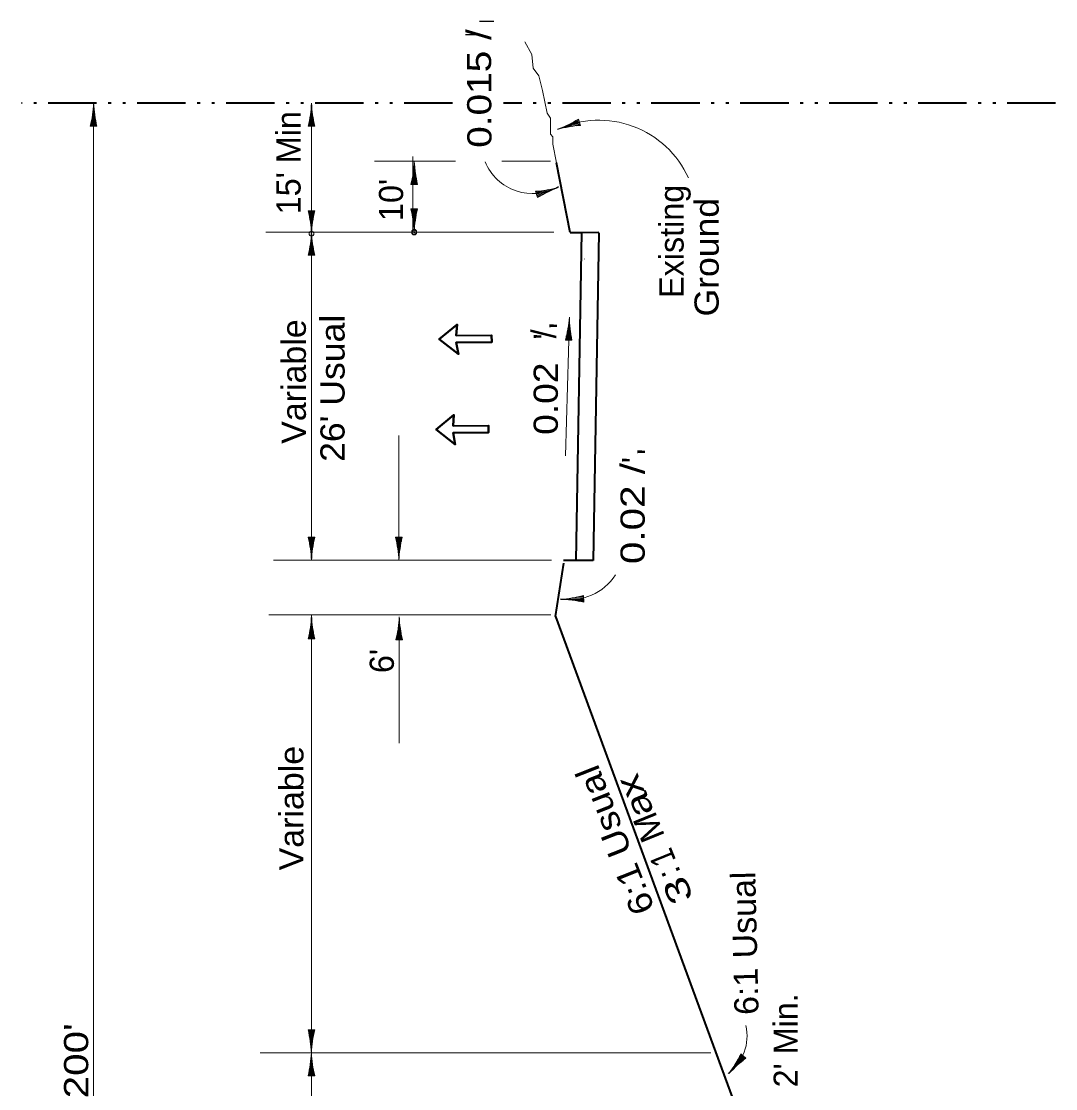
# Model space of a CAD drawing. Extents: x 2363427 to 2368559, y 6957299 to 6980140.
# Drawn here: x 2364654 to 2365253, y 6959501 to 6960119 of the extents above; entities that cross this region are included whole.
import ezdxf
from ezdxf.enums import TextEntityAlignment as Align

# ---------------------------------------------------------------- set-up
doc = ezdxf.new("R2010")
doc.units = 0
doc.header["$LTSCALE"] = 5.6
doc.header["$PDMODE"] = 32
doc.header["$PDSIZE"] = 2.8
doc.linetypes.add('DASH_DOUBLE_DOT', pattern=[9.2, 5, -1.2, 0.3, -1.2, 0.3, -1.2])
doc.linetypes.add('MEDIUM_DASHED', pattern=[4.5, 3, -1.5])
for name, color, linetype, lineweight in [('1', 7, 'Continuous', 13), ('3', 7, 'Continuous', 35), ('4', 7, 'Continuous', 13), ('40', 7, 'Continuous', 35), ('48', 7, 'Continuous', 25), ('6', 7, 'Continuous', 13), ('8', 7, 'Continuous', 13)]:
    doc.layers.add(name, color=color, linetype=linetype, lineweight=lineweight)

msp = doc.modelspace()

# ---------------------------------------------------------------- linework, layer by layer
at = {"layer": '1'}
for p, q in [((2364977.084, 6960060.54), (2364965.138, 6960056.646)), ((2364977.239, 6960060.065), (2364969.053, 6960057.397)), ((2364976.929, 6960061.015), (2364969.941, 6960058.737)), ((2364976.774, 6960061.491), (2364972.708, 6960060.165)), ((2364976.619, 6960061.967), (2364975.112, 6960061.475)), ((2364976.51, 6960062.299), (2364977.698, 6960058.657)), ((2364977.394, 6960059.589), (2364972.772, 6960058.083)), ((2364977.549, 6960059.114), (2364975.284, 6960058.376)), ((2365071.926, 6959519.653), (2365063.908, 6959509.979)), ((2365072.31, 6959519.333), (2365066.816, 6959512.705)), ((2365071.54, 6959519.971), (2365066.85, 6959514.313)), ((2365071.156, 6959520.291), (2365068.426, 6959516.998)), ((2365072.696, 6959519.015), (2365069.592, 6959515.271)), ((2365070.77, 6959520.609), (2365069.759, 6959519.389)), ((2365070.501, 6959520.833), (2365073.45, 6959518.389)), ((2365073.08, 6959518.695), (2365071.56, 6959516.861))]:
    msp.add_line(p, q, dxfattribs=at)
at = {"layer": '1', "linetype": 'MEDIUM_DASHED'}
msp.add_lwpolyline([(2364963.772, 6960036.875), (2364961.718, 6960047.707), (2364961.718, 6960052.041), (2364960.366, 6960053.487), (2364960.366, 6960059.267), (2364960.366, 6960062.879), (2364958.338, 6960065.769), (2364956.986, 6960072.271), (2364955.634, 6960078.773), (2364953.605, 6960087.443), (2364950.225, 6960091.777), (2364949.549, 6960099.725), (2364945.492, 6960106.949)], dxfattribs=at)
at = {"layer": '1'}
for centre, radius, start, end in [((2364988.349, 6960004.852), 56.809, 24.26661, 114.90949), ((2364938.688, 6960123.814), 72.212, 290.89929, 301.58534), ((2364983.396, 6959986.67), 72.212, 94.52612, 105.21217), ((2365047.078, 6959531.078), 27.012, 306.76831, 13.14994), ((2365005.667, 6959552.632), 72.212, 323.18777, 333.87382), ((2365116.722, 6959460.577), 72.212, 126.81461, 137.50066)]:
    msp.add_arc(centre, radius, start, end, dxfattribs=at)
at = {"layer": '3', "linetype": 'DASH_DOUBLE_DOT'}
for p, q in [((2364903.617, 6960071.447), (2364653.955, 6960071.447)), ((2365252.758, 6960071.447), (2364933.046, 6960071.447))]:
    msp.add_line(p, q, dxfattribs=at)
at = {"layer": '3'}
for p, q in [((2364971.652, 6959996.693), (2364963.772, 6960036.875)), ((2364971.652, 6959996.693), (2364978.244, 6959996.665)), ((2364978.244, 6959996.665), (2364974.924, 6959806.63)), ((2364978.244, 6959996.665), (2364988.247, 6959996.757)), ((2364988.242, 6959996.49), (2364984.924, 6959806.542)), ((2364984.925, 6959806.629), (2364967.902, 6959806.631)), ((2364963.114, 6959774.14), (2364968.1, 6959804.984)), ((2364963.114, 6959774.14), (2365067.63, 6959490.027))]:
    msp.add_line(p, q, dxfattribs=at)
at = {"layer": '3', "lineweight": 13}
for p, q in [((2364962.238, 6959996.759), (2364795.534, 6959996.759)), ((2364978.248, 6959996.709), (2364978.244, 6959996.665)), ((2364980.071, 6959981.22), (2364979.949, 6959981.334)), ((2364968.937, 6959867.329), (2364971.212, 6959947.583)), ((2364970.4, 6959934.289), (2364970.644, 6959942.895)), ((2364970.9, 6959934.275), (2364971.256, 6959946.833)), ((2364969.401, 6959934.317), (2364969.468, 6959936.697)), ((2364969.9, 6959934.303), (2364970.038, 6959939.163)), ((2364971.4, 6959934.261), (2364971.608, 6959941.607)), ((2364971.9, 6959934.247), (2364972.021, 6959938.521)), ((2364972.75, 6959934.223), (2364968.921, 6959934.331)), ((2364972.4, 6959934.233), (2364972.444, 6959935.817)), ((2364960.92, 6959806.759), (2364799.934, 6959806.759)), ((2364969.506, 6959806.533), (2364969.506, 6959806.631)), ((2365053.112, 6959521.447), (2364792.272, 6959521.447))]:
    msp.add_line(p, q, dxfattribs=at)
for centre, start, end in [((2364899.219, 6959953.208), 344.84626, 355.53231), ((2365043.409, 6959949.119), 181.21943, 191.90548)]:
    msp.add_arc(centre, 72.212, start, end, dxfattribs=at)
at = {"layer": '4', "lineweight": 25}
for p, q in [((2364927.449, 6960118.911), (2364919.288, 6960118.911)), ((2364919.32, 6960111.075), (2364911.159, 6960111.075))]:
    msp.add_line(p, q, dxfattribs=at)
at = {"layer": '4'}
for p, q in [((2364905.299, 6960037.877), (2364858.467, 6960037.877)), ((2364881.36, 6960024.479), (2364881.36, 6960037.043)), ((2364881.36, 6960024.479), (2364881.36, 6960037.043)), ((2364960.343, 6960037.877), (2364932.205, 6960037.877)), ((2364880.86, 6960024.479), (2364880.86, 6960031.829)), ((2364880.86, 6960024.479), (2364880.86, 6960031.829)), ((2364881.86, 6960024.479), (2364881.86, 6960033.088)), ((2364881.86, 6960024.479), (2364881.86, 6960033.088)), ((2364882.36, 6960024.479), (2364882.36, 6960029.341)), ((2364882.36, 6960024.479), (2364882.36, 6960029.341)), ((2364879.51, 6960024.479), (2364883.34, 6960024.479)), ((2364879.51, 6960024.479), (2364883.34, 6960024.479)), ((2364879.86, 6960024.479), (2364879.86, 6960026.063)), ((2364879.86, 6960024.479), (2364879.86, 6960026.063)), ((2364880.36, 6960024.479), (2364880.36, 6960028.755)), ((2364880.36, 6960024.479), (2364880.36, 6960028.755)), ((2364882.86, 6960024.479), (2364882.86, 6960026.86)), ((2364882.86, 6960024.479), (2364882.86, 6960026.86)), ((2364951.65, 6960020.478), (2364952.815, 6960016.829)), ((2364951.757, 6960020.145), (2364953.267, 6960020.627)), ((2364951.909, 6960019.668), (2364955.983, 6960020.969)), ((2364952.061, 6960019.192), (2364959.062, 6960021.429)), ((2364952.213, 6960018.715), (2364964.181, 6960022.539)), ((2364952.365, 6960018.239), (2364960.567, 6960020.859)), ((2364952.517, 6960017.763), (2364957.149, 6960019.243)), ((2364952.669, 6960017.287), (2364954.938, 6960018.011)), ((2364883.319, 6960010.286), (2364879.489, 6960010.286)), ((2364883.319, 6960010.286), (2364879.489, 6960010.286)), ((2364879.969, 6960010.286), (2364879.969, 6960007.904)), ((2364879.969, 6960010.286), (2364879.969, 6960007.904)), ((2364880.469, 6960010.286), (2364880.469, 6960005.424)), ((2364880.469, 6960010.286), (2364880.469, 6960005.424)), ((2364880.969, 6960010.286), (2364880.969, 6960001.676)), ((2364880.969, 6960010.286), (2364880.969, 6960001.676)), ((2364881.469, 6960010.286), (2364881.469, 6959997.722)), ((2364881.469, 6960010.286), (2364881.469, 6959997.722)), ((2364881.969, 6960010.286), (2364881.969, 6960002.936)), ((2364881.969, 6960010.286), (2364881.969, 6960002.936)), ((2364882.469, 6960010.286), (2364882.469, 6960006.009)), ((2364882.469, 6960010.286), (2364882.469, 6960006.009)), ((2364882.969, 6960010.286), (2364882.969, 6960008.7)), ((2364882.969, 6960010.286), (2364882.969, 6960008.7)), ((2364979.486, 6959784.5), (2364966.926, 6959784.172)), ((2364979.499, 6959784), (2364970.891, 6959783.775)), ((2364979.473, 6959784.999), (2364972.125, 6959784.808)), ((2364979.512, 6959783.5), (2364974.651, 6959783.373)), ((2364979.459, 6959785.499), (2364975.185, 6959785.388)), ((2364979.524, 6959782.999), (2364977.144, 6959782.938)), ((2364979.446, 6959785.999), (2364977.862, 6959785.957)), ((2364979.437, 6959786.348), (2364979.537, 6959782.52)), ((2364960.496, 6959775.212), (2364797.312, 6959775.212)), ((2364872.295, 6959760.66), (2364872.295, 6959769.269)), ((2364872.729, 6959700.712), (2364872.729, 6959773.971)), ((2364872.795, 6959760.66), (2364872.795, 6959773.224)), ((2364871.795, 6959760.66), (2364871.795, 6959765.522)), ((2364873.295, 6959760.66), (2364873.295, 6959768.01)), ((2364873.795, 6959760.66), (2364873.795, 6959764.936)), ((2364874.645, 6959760.66), (2364870.815, 6959760.66)), ((2364871.295, 6959760.66), (2364871.295, 6959763.041)), ((2364874.295, 6959760.66), (2364874.295, 6959762.244))]:
    msp.add_line(p, q, dxfattribs=at)
for centre, radius, start, end in [((2364809.302, 6960041.373), 72.212, 346.47039, 357.15644), ((2364809.302, 6960041.373), 72.212, 346.47039, 357.15644), ((2364953.549, 6960041.373), 72.212, 182.84356, 193.52961), ((2364953.549, 6960041.373), 72.212, 182.84356, 193.52961), ((2364949.892, 6960048.768), 29.635, 202.18381, 300.37926), ((2364946.377, 6960092.499), 72.212, 274.18736, 284.87341), ((2364990.273, 6959955.093), 72.212, 110.56052, 121.24657), ((2364809.281, 6959993.393), 72.212, 2.84356, 13.52961), ((2364809.281, 6959993.393), 72.212, 2.84356, 13.52961), ((2364953.528, 6959993.393), 72.212, 166.47039, 177.15644), ((2364953.528, 6959993.393), 72.212, 166.47039, 177.15644), ((2364971.404, 6959815.634), 31.768, 260.35981, 326.74144), ((2364960.716, 6959856.093), 72.212, 274.33889, 285.02494), ((2364964.481, 6959711.895), 72.212, 77.96572, 88.65177), ((2364800.606, 6959777.553), 72.212, 346.47039, 357.15644), ((2364944.853, 6959777.553), 72.212, 182.84356, 193.52961)]:
    msp.add_arc(centre, radius, start, end, dxfattribs=at)
for p in [(2364881.405, 6959996.974), (2364881.405, 6959996.573)]:
    msp.add_point(p, dxfattribs=at)
at = {"layer": '40'}
for p, q in [((2364905.704, 6959937.017), (2364926.209, 6959937.211)), ((2364903.884, 6959884.625), (2364924.389, 6959884.82))]:
    msp.add_line(p, q, dxfattribs=at)
for points in [[(2364905.704, 6959937.017), (2364906.236, 6959943.331), (2364895.849, 6959934.797), (2364906.949, 6959926.194), (2364905.742, 6959932.921)], [(2364905.742, 6959932.921), (2364926.246, 6959933.117), (2364926.209, 6959937.211)], [(2364903.884, 6959884.625), (2364904.416, 6959890.94), (2364894.029, 6959882.405), (2364905.129, 6959873.803), (2364903.922, 6959880.53)], [(2364903.922, 6959880.53), (2364924.426, 6959880.725), (2364924.389, 6959884.82)]]:
    msp.add_lwpolyline(points, dxfattribs=at)
at = {"layer": '48', "lineweight": 13}
msp.add_lwpolyline([(2364974.924, 6959806.63), (2364984.924, 6959806.542), (2364988.242, 6959996.49), (2364978.244, 6959996.665)], close=True, dxfattribs=at)
at = {"layer": '6'}
for p, q in [((2364695.362, 6960058.135), (2364695.362, 6960066.745)), ((2364695.798, 6959070.731), (2364695.798, 6960071.447)), ((2364695.862, 6960058.135), (2364695.862, 6960070.699)), ((2364821.498, 6960058.135), (2364821.498, 6960066.745)), ((2364821.934, 6959995.911), (2364821.934, 6960071.447)), ((2364821.998, 6960058.135), (2364821.998, 6960070.699)), ((2364694.362, 6960058.135), (2364694.362, 6960060.517)), ((2364694.862, 6960058.135), (2364694.862, 6960062.997)), ((2364696.362, 6960058.135), (2364696.362, 6960065.485)), ((2364696.862, 6960058.135), (2364696.862, 6960062.411)), ((2364820.498, 6960058.135), (2364820.498, 6960060.517)), ((2364820.998, 6960058.135), (2364820.998, 6960062.997)), ((2364822.498, 6960058.135), (2364822.498, 6960065.485)), ((2364822.998, 6960058.135), (2364822.998, 6960062.411)), ((2364697.712, 6960058.135), (2364693.882, 6960058.135)), ((2364697.362, 6960058.135), (2364697.362, 6960059.721)), ((2364823.848, 6960058.135), (2364820.018, 6960058.135)), ((2364823.498, 6960058.135), (2364823.498, 6960059.721)), ((2364880.61, 6959996.573), (2364880.61, 6960040.713)), ((2364820.018, 6960009.223), (2364823.848, 6960009.223)), ((2364820.368, 6960009.223), (2364820.368, 6960007.639)), ((2364820.868, 6960009.223), (2364820.868, 6960004.947)), ((2364821.368, 6960009.223), (2364821.368, 6960001.873)), ((2364821.868, 6960009.223), (2364821.868, 6959996.659)), ((2364822.368, 6960009.223), (2364822.368, 6960000.613)), ((2364822.868, 6960009.223), (2364822.868, 6960004.361)), ((2364823.368, 6960009.223), (2364823.368, 6960006.841)), ((2364821.498, 6959983.447), (2364821.498, 6959992.057)), ((2364821.934, 6959806.759), (2364821.934, 6959996.759)), ((2364821.998, 6959983.447), (2364821.998, 6959996.011)), ((2364820.498, 6959983.447), (2364820.498, 6959985.829)), ((2364820.998, 6959983.447), (2364820.998, 6959988.309)), ((2364822.498, 6959983.447), (2364822.498, 6959990.797)), ((2364822.998, 6959983.447), (2364822.998, 6959987.723)), ((2364823.848, 6959983.447), (2364820.018, 6959983.447)), ((2364823.498, 6959983.447), (2364823.498, 6959985.031)), ((2364872.532, 6959806.759), (2364872.532, 6959879.019)), ((2364820.018, 6959820.069), (2364823.848, 6959820.069)), ((2364820.368, 6959820.069), (2364820.368, 6959818.485)), ((2364820.868, 6959820.069), (2364820.868, 6959815.793)), ((2364821.368, 6959820.069), (2364821.368, 6959812.719)), ((2364821.868, 6959820.069), (2364821.868, 6959807.505)), ((2364822.368, 6959820.069), (2364822.368, 6959811.461)), ((2364822.868, 6959820.069), (2364822.868, 6959815.207)), ((2364823.368, 6959820.069), (2364823.368, 6959817.689)), ((2364870.616, 6959820.069), (2364874.446, 6959820.069)), ((2364870.966, 6959820.069), (2364870.966, 6959818.485)), ((2364871.466, 6959820.069), (2364871.466, 6959815.793)), ((2364871.966, 6959820.069), (2364871.966, 6959812.719)), ((2364872.466, 6959820.069), (2364872.466, 6959807.505)), ((2364872.966, 6959820.069), (2364872.966, 6959811.461)), ((2364873.466, 6959820.069), (2364873.466, 6959815.207)), ((2364873.966, 6959820.069), (2364873.966, 6959817.689)), ((2364821.498, 6959761.209), (2364821.5, 6959769.819)), ((2364821.998, 6959761.209), (2364822.002, 6959773.773)), ((2364820.498, 6959761.209), (2364820.498, 6959763.591)), ((2364820.998, 6959761.209), (2364820.999, 6959766.071)), ((2364822.498, 6959761.209), (2364822.5, 6959768.559)), ((2364822.998, 6959761.209), (2364822.999, 6959765.485)), ((2364823.848, 6959761.209), (2364820.018, 6959761.209)), ((2364823.498, 6959761.209), (2364823.498, 6959762.793)), ((2364819.945, 6959534.759), (2364823.775, 6959534.757)), ((2364820.295, 6959534.759), (2364820.294, 6959533.173)), ((2364820.795, 6959534.759), (2364820.794, 6959530.483)), ((2364821.295, 6959534.759), (2364821.292, 6959527.409)), ((2364821.795, 6959534.759), (2364821.791, 6959522.195)), ((2364822.295, 6959534.759), (2364822.292, 6959526.149)), ((2364822.795, 6959534.759), (2364822.794, 6959529.897)), ((2364823.295, 6959534.757), (2364823.294, 6959532.377)), ((2364821.421, 6959508.135), (2364821.421, 6959516.745)), ((2364821.921, 6959508.135), (2364821.921, 6959520.699)), ((2364820.421, 6959508.135), (2364820.421, 6959510.517)), ((2364820.921, 6959508.135), (2364820.921, 6959512.997)), ((2364822.421, 6959508.135), (2364822.421, 6959515.485)), ((2364822.921, 6959508.135), (2364822.921, 6959512.411)), ((2364823.421, 6959508.135), (2364823.421, 6959509.72)), ((2364823.771, 6959508.135), (2364819.941, 6959508.135))]:
    msp.add_line(p, q, dxfattribs=at)
for points in [[(2364821.934, 6959521.019), (2364821.856, 6959521.447), (2364821.931, 6959775.212)], [(2364821.856, 6959134.019), (2364821.856, 6959371.419), (2364821.856, 6959521.447)]]:
    msp.add_lwpolyline(points, dxfattribs=at)
for centre, start, end in [((2364623.674, 6960075.029), 346.47039, 357.15644), ((2364767.921, 6960075.029), 182.84356, 193.52961), ((2364749.81, 6960075.029), 346.47039, 357.15644), ((2364894.057, 6960075.029), 182.84356, 193.52961), ((2364749.81, 6959992.329), 2.84356, 13.52961), ((2364894.057, 6959992.329), 166.47039, 177.15644), ((2364749.81, 6960000.341), 346.47039, 357.15644), ((2364894.057, 6960000.341), 182.84356, 193.52961), ((2364749.81, 6959803.176), 2.84356, 13.52961), ((2364894.057, 6959803.176), 166.47039, 177.15644), ((2364800.408, 6959803.176), 2.84356, 13.52961), ((2364944.655, 6959803.176), 166.47039, 177.15644), ((2364749.814, 6959778.125), 346.45333, 357.13938), ((2364894.061, 6959778.082), 182.82649, 193.51254), ((2364749.731, 6959517.886), 2.82649, 13.51254), ((2364893.978, 6959517.843), 166.45333, 177.13938), ((2364749.732, 6959525.029), 346.47039, 357.15644), ((2364893.98, 6959525.029), 182.84356, 193.52961)]:
    msp.add_arc(centre, 72.212, start, end, dxfattribs=at)
msp.add_point((2364821.934, 6959995.911), dxfattribs=at)
at = {"layer": '8', "lineweight": 40}
for points in [[(2364895.849, 6959934.797), (2364906.236, 6959943.331), (2364905.704, 6959937.017), (2364926.209, 6959937.211), (2364926.246, 6959933.117), (2364905.742, 6959932.921), (2364906.949, 6959926.194)], [(2364894.029, 6959882.405), (2364904.416, 6959890.94), (2364903.884, 6959884.625), (2364924.389, 6959884.82), (2364924.426, 6959880.725), (2364903.922, 6959880.53), (2364905.129, 6959873.803)]]:
    msp.add_lwpolyline(points, close=True, dxfattribs=at)

# ---------------------------------------------------------------- texts
at = {"layer": '3'}
for s, p in [("'", (2364973.698, 6959942.574)), ('/', (2364963.421, 6959937.893)), ("'", (2364964.624, 6959936.369)), ("'", (2365024.646, 6959869.601)), ("'", (2365015.728, 6959864.771))]:
    msp.add_text(s, height=14, rotation=90, dxfattribs=at).set_placement(p, align=Align.CENTER)
at = {"layer": '4'}
for s, rotation, width, p in [('0.015 /', 90.292, 1.2, (2364925.998, 6960080.046)), ('Ground', 90, 1.1, (2365057.67, 6959982.293)), ('Variable', 90, 1.05, (2364818.673, 6959910.254)), ("26' Usual", 90, 1.1, (2364841.093, 6959906.341)), ('0.02', 90, 1.15, (2364964.558, 6959900.333)), ('0.02 /', 90, 1.25, (2365014.852, 6959833.81)), ('Variable', 90, 1.05, (2364817.272, 6959663.173)), ('6:1 Usual', 111.596, 1.15, (2365004.189, 6959647.13)), ('x', 112.184, 1.35, (2365012.759, 6959678.31)), ('a', 112.184, 1.3, (2365017.868, 6959667.493)), ('M', 112.184, 1.05, (2365023.636, 6959654.624)), ('1', 112.184, 0.85, (2365031.513, 6959637.07)), ('3', 112.184, 1.45, (2365040.485, 6959618.09)), ('6:1 Usual', 91.404, 1.05, (2365079.818, 6959585.053)), ("200'", 90, 1.25, (2364692.658, 6959516.82))]:
    msp.add_text(s, height=14, rotation=rotation, dxfattribs=dict(at, width=width)).set_placement(p, align=Align.CENTER)
for s, rotation, p in [("15' Min", 90, (2364815.61, 6960037.034)), ("10' ", 90, (2364874.973, 6960018.077)), ('Existing ', 90, (2365037.358, 6959994.094)), ("6' ", 90, (2364869.618, 6959750.994)), (':', 112.184, (2365034.918, 6959628.329)), ("2' Min.", 90, (2365103.47, 6959528.668))]:
    msp.add_text(s, height=14, rotation=rotation, dxfattribs=at).set_placement(p, align=Align.CENTER)

doc.saveas('drawing.dxf')
